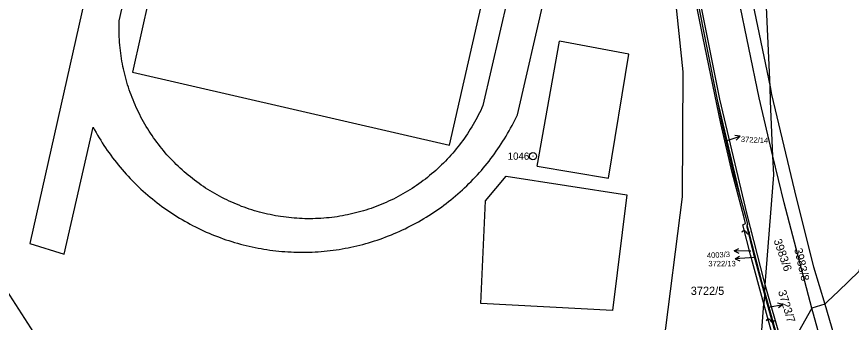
# Model space of a CAD drawing. Extents: x -747779 to -747197, y -965543 to -964919.
# Drawn here: x -747670.1 to -747496.8, y -965237.8 to -965174.5 of the extents above; entities that cross this region are included whole.
import ezdxf

# ---------------------------------------------------------------- set-up
doc = ezdxf.new("R2010")
doc.units = 0
for name, color, linetype in [('Hranice parcel', 7, 'Continuous'), ('Parcelní čísla', 7, 'Continuous'), ('Pop  PČ popisy', 7, 'Continuous'), ('Vnitřní kresba', 7, 'Continuous'), ('Značky bodu BP', 7, 'Continuous'), ('Značky budov', 7, 'Continuous')]:
    doc.layers.add(name, color=color, linetype=linetype)

msp = doc.modelspace()

# ---------------------------------------------------------------- linework, layer by layer
at = {"layer": 'Hranice parcel'}
for p, q in [((-747530.21, -965163.73), (-747524.64, -965191.71)), ((-747524.64, -965191.71), (-747519.84, -965211.9)), ((-747681.26, -965217.18), (-747664.09, -965243.73)), ((-747514.78, -965232.07), (-747514.92, -965233.94)), ((-747514.75, -965231.66), (-747514.78, -965232.07)), ((-747514.75, -965231.66), (-747511.04, -965244.8)), ((-747502.29, -965234.04), (-747505, -965234.87))]:
    msp.add_line(p, q, dxfattribs=at)
for points in [[(-747513.05, -965203.34), (-747515.92, -965191.31), (-747520.21, -965170.52), (-747525.67, -965137.7), (-747528.61, -965118.1), (-747531.3, -965092.39), (-747532.87, -965073.71), (-747533.98, -965052.7), (-747534.7, -965029.05), (-747536.67, -965009.71), (-747536.72, -965001.18), (-747536.76, -964995.31), (-747536.77, -964994.35), (-747535.07, -964979.91), (-747534.55, -964969.6), (-747535.47, -964951.02), (-747536.46, -964942.86), (-747538.19, -964936.51)], [(-747514.92, -965233.94), (-747517.71, -965223.84), (-747519.3, -965217.6), (-747518.74, -965217.36), (-747518.99, -965216.17), (-747521.54, -965206.73), (-747523.88, -965196.63), (-747527.58, -965178.59), (-747529.34, -965169.85), (-747531.71, -965157.18), (-747535.79, -965130.78), (-747546.28, -965062.23), (-747546.46, -965062.18)], [(-747535.74, -965242.71), (-747531.85, -965211.79), (-747531.66, -965185.87), (-747538.81, -965117.67), (-747546.28, -965074.93), (-747546.46, -965062.18)], [(-747513.65, -965189), (-747514.35, -965172.47), (-747514.45, -965170.1), (-747522.38, -965119.84), (-747530.45, -965066.92)], [(-747530.45, -965066.92), (-747530.18, -965073.53), (-747528.7, -965091.91), (-747525.96, -965117.41), (-747523.14, -965137.31), (-747517.53, -965170.11), (-747513.65, -965189)], [(-747487.95, -965176.49), (-747489.26, -965206.38), (-747495.23, -965227.3), (-747499.46, -965231.34), (-747501.73, -965233.5), (-747502.29, -965234.04)], [(-747513.05, -965203.34), (-747513.53, -965191.97), (-747513.65, -965189)], [(-747513.65, -965189), (-747513.32, -965190.63), (-747508.25, -965211.99), (-747504.62, -965226.28), (-747502.29, -965234.04)], [(-747524.64, -965191.71), (-747523.65, -965196.56), (-747521.27, -965206.66), (-747519.84, -965211.9)], [(-747514.75, -965231.66), (-747514.63, -965230.04), (-747512.88, -965207.25), (-747513.05, -965203.34)], [(-747505, -965234.87), (-747510.73, -965213.04), (-747513.05, -965203.34)], [(-747519.84, -965211.9), (-747518.7, -965216.08), (-747518.34, -965217.56), (-747518.44, -965217.6)], [(-747518.44, -965217.6), (-747518.48, -965218.05), (-747517.11, -965223.71), (-747514.78, -965232.07)], [(-747518.44, -965217.6), (-747515.39, -965229.37), (-747514.75, -965231.66)], [(-747514.78, -965232.07), (-747511.25, -965244.76), (-747511.35, -965244.91)], [(-747516.6, -965252.37), (-747515.34, -965239.4), (-747514.92, -965233.94)], [(-747516.6, -965252.37), (-747515.81, -965251.13), (-747515.95, -965251.03), (-747511.95, -965244.73), (-747514.92, -965233.94)], [(-747505, -965234.87), (-747510.48, -965244.69), (-747511.04, -965244.8)]]:
    msp.add_lwpolyline(points, dxfattribs=at)
at = {"layer": 'Pop  PČ popisy'}
for p, q in [((-747519.87, -965199.26), (-747520.97, -965199.1)), ((-747522.72, -965200.19), (-747519.87, -965199.26)), ((-747519.87, -965199.26), (-747520.66, -965200.05)), ((-747521.11, -965222.98), (-747520.1, -965222.49)), ((-747518.11, -965223.03), (-747521.11, -965222.98)), ((-747521.11, -965222.98), (-747520.12, -965223.5)), ((-747517.64, -965223.05), (-747518.11, -965223.03)), ((-747520.91, -965224.65), (-747519.95, -965224.08)), ((-747517.92, -965224.44), (-747520.91, -965224.65)), ((-747520.91, -965224.65), (-747519.88, -965225.08)), ((-747516.84, -965224.36), (-747517.92, -965224.44)), ((-747510.99, -965234.12), (-747512.07, -965233.82)), ((-747513.94, -965234.69), (-747510.99, -965234.12)), ((-747510.99, -965234.12), (-747511.88, -965234.8))]:
    msp.add_line(p, q, dxfattribs=at)
at = {"layer": 'Vnitřní kresba'}
for p, q in [((-747632.83, -965068.52), (-747667.34, -965221.45)), ((-747623.25, -965083.71), (-747646.03, -965185.94)), ((-747648.77, -965175.31), (-747629.51, -965090.06)), ((-747580.16, -965201.09), (-747556.88, -965098.9)), ((-747554.23, -965109.88), (-747573.25, -965192.86)), ((-747566.1, -965194.79), (-747546.86, -965111.5)), ((-747524.05, -965191.58), (-747529.66, -965163.6)), ((-747561.99, -965205.42), (-747557.35, -965179.56)), ((-747542.98, -965182.26), (-747557.35, -965179.56)), ((-747547.21, -965207.91), (-747542.98, -965182.26)), ((-747646.03, -965185.94), (-747580.16, -965201.09)), ((-747518.39, -965215.47), (-747524.05, -965191.58)), ((-747660.21, -965223.66), (-747654.19, -965197.38)), ((-747561.99, -965205.42), (-747547.21, -965207.91)), ((-747572.74, -965212.66), (-747568.4, -965207.5)), ((-747568.4, -965207.5), (-747543.4, -965211.4)), ((-747573.69, -965233.88), (-747572.74, -965212.66)), ((-747543.4, -965211.4), (-747546.37, -965235.34)), ((-747514.86, -965229.21), (-747518.39, -965215.47)), ((-747667.34, -965221.45), (-747660.21, -965223.66)), ((-747514.63, -965230.04), (-747514.86, -965229.21)), ((-747510.48, -965244.69), (-747514.63, -965230.04)), ((-747546.37, -965235.34), (-747573.69, -965233.88)), ((-747500.75, -965249.85), (-747505, -965234.87)), ((-747502.29, -965234.04), (-747497.81, -965248.91))]:
    msp.add_line(p, q, dxfattribs=at)
for points in [[(-747619.62, -965214.97), (-747620.16, -965214.82), (-747620.7, -965214.67), (-747621.23, -965214.5), (-747621.77, -965214.33), (-747622.3, -965214.15), (-747622.82, -965213.96), (-747623.35, -965213.77), (-747623.87, -965213.56), (-747624.39, -965213.35), (-747624.9, -965213.14), (-747625.42, -965212.91), (-747625.93, -965212.68), (-747626.43, -965212.44), (-747626.93, -965212.2), (-747627.43, -965211.94), (-747627.93, -965211.68), (-747628.42, -965211.42), (-747628.91, -965211.14), (-747629.39, -965210.86), (-747629.87, -965210.57), (-747630.35, -965210.28), (-747630.82, -965209.98), (-747631.28, -965209.67), (-747631.75, -965209.36), (-747632.2, -965209.04), (-747632.66, -965208.71), (-747633.11, -965208.37), (-747633.55, -965208.03), (-747633.99, -965207.69), (-747634.43, -965207.33), (-747634.85, -965206.98), (-747635.28, -965206.61), (-747635.7, -965206.24), (-747636.11, -965205.86), (-747636.52, -965205.48), (-747636.92, -965205.09), (-747637.32, -965204.7), (-747637.71, -965204.3), (-747638.1, -965203.89), (-747638.48, -965203.48), (-747638.85, -965203.07), (-747639.22, -965202.65), (-747639.58, -965202.22), (-747639.94, -965201.79), (-747640.29, -965201.35), (-747640.63, -965200.91), (-747640.97, -965200.47), (-747641.3, -965200.02), (-747641.63, -965199.56), (-747641.95, -965199.1), (-747642.26, -965198.64), (-747642.56, -965198.17), (-747642.86, -965197.69), (-747643.15, -965197.22), (-747643.44, -965196.73), (-747643.71, -965196.25), (-747643.99, -965195.76), (-747644.25, -965195.27), (-747644.51, -965194.77), (-747644.76, -965194.27), (-747645, -965193.77), (-747645.24, -965193.26), (-747645.47, -965192.75), (-747645.69, -965192.23), (-747645.9, -965191.72), (-747646.11, -965191.2), (-747646.31, -965190.68), (-747646.5, -965190.15), (-747646.68, -965189.62), (-747646.86, -965189.09), (-747647.03, -965188.56), (-747647.19, -965188.02), (-747647.35, -965187.48), (-747647.49, -965186.95), (-747647.63, -965186.4), (-747647.76, -965185.86), (-747647.89, -965185.31), (-747648, -965184.77), (-747648.11, -965184.22), (-747648.21, -965183.67), (-747648.3, -965183.11), (-747648.39, -965182.56), (-747648.46, -965182.01), (-747648.53, -965181.45), (-747648.59, -965180.9), (-747648.65, -965180.34), (-747648.69, -965179.78), (-747648.73, -965179.22), (-747648.76, -965178.67), (-747648.78, -965178.11), (-747648.8, -965177.55), (-747648.8, -965176.99), (-747648.8, -965176.43), (-747648.79, -965175.87), (-747648.77, -965175.31)], [(-747573.25, -965192.86), (-747573.48, -965193.37), (-747573.72, -965193.88), (-747573.96, -965194.38), (-747574.21, -965194.88), (-747574.47, -965195.38), (-747574.74, -965195.87), (-747575.01, -965196.36), (-747575.29, -965196.84), (-747575.58, -965197.32), (-747575.87, -965197.8), (-747576.17, -965198.27), (-747576.48, -965198.74), (-747576.79, -965199.2), (-747577.11, -965199.66), (-747577.44, -965200.11), (-747577.77, -965200.56), (-747578.11, -965201.01), (-747578.45, -965201.45), (-747578.81, -965201.88), (-747579.16, -965202.31), (-747579.53, -965202.74), (-747579.9, -965203.16), (-747580.27, -965203.57), (-747580.65, -965203.98), (-747581.04, -965204.39), (-747581.43, -965204.79), (-747581.83, -965205.18), (-747582.24, -965205.57), (-747582.65, -965205.95), (-747583.06, -965206.32), (-747583.48, -965206.69), (-747583.91, -965207.05), (-747584.34, -965207.41), (-747584.77, -965207.76), (-747585.21, -965208.11), (-747585.66, -965208.45), (-747586.11, -965208.78), (-747586.56, -965209.1), (-747587.02, -965209.43), (-747587.48, -965209.74), (-747587.95, -965210.04), (-747588.42, -965210.34), (-747588.9, -965210.64), (-747589.38, -965210.92), (-747589.87, -965211.2), (-747590.35, -965211.47), (-747590.85, -965211.74), (-747591.34, -965212), (-747591.84, -965212.25), (-747592.35, -965212.49), (-747592.85, -965212.73), (-747593.36, -965212.96), (-747593.88, -965213.19), (-747594.39, -965213.4), (-747594.91, -965213.61), (-747595.43, -965213.81), (-747595.96, -965214), (-747596.49, -965214.19), (-747597.02, -965214.37), (-747597.55, -965214.54), (-747598.08, -965214.7), (-747598.62, -965214.86), (-747599.16, -965215), (-747599.7, -965215.14), (-747600.25, -965215.28), (-747600.79, -965215.4), (-747601.34, -965215.52), (-747601.89, -965215.63), (-747602.44, -965215.73), (-747602.99, -965215.82), (-747603.54, -965215.91), (-747604.09, -965215.99), (-747604.65, -965216.06), (-747605.21, -965216.12), (-747605.76, -965216.18), (-747606.32, -965216.22), (-747606.88, -965216.26), (-747607.44, -965216.29), (-747608, -965216.32), (-747608.56, -965216.33), (-747609.11, -965216.34), (-747609.67, -965216.34), (-747610.23, -965216.33), (-747610.79, -965216.31), (-747611.35, -965216.29), (-747611.91, -965216.25), (-747612.47, -965216.21), (-747613.03, -965216.16), (-747613.58, -965216.11), (-747614.14, -965216.04), (-747614.69, -965215.97), (-747615.25, -965215.89), (-747615.8, -965215.8), (-747616.35, -965215.71), (-747616.9, -965215.61), (-747617.45, -965215.49), (-747617.99, -965215.38), (-747618.54, -965215.25), (-747619.08, -965215.11), (-747619.62, -965214.97)], [(-747601.26, -965222.35), (-747600.65, -965222.22), (-747600.04, -965222.09), (-747599.42, -965221.95), (-747598.82, -965221.8), (-747598.21, -965221.65), (-747597.6, -965221.48), (-747597, -965221.31), (-747596.4, -965221.13), (-747595.8, -965220.95), (-747595.21, -965220.75), (-747594.61, -965220.55), (-747594.02, -965220.34), (-747593.44, -965220.12), (-747592.85, -965219.9), (-747592.27, -965219.67), (-747591.69, -965219.43), (-747591.11, -965219.18), (-747590.54, -965218.93), (-747589.97, -965218.67), (-747589.41, -965218.4), (-747588.84, -965218.12), (-747588.28, -965217.84), (-747587.73, -965217.55), (-747587.18, -965217.26), (-747586.63, -965216.95), (-747586.08, -965216.64), (-747585.54, -965216.32), (-747585.01, -965216), (-747584.47, -965215.67), (-747583.95, -965215.33), (-747583.42, -965214.98), (-747582.91, -965214.63), (-747582.39, -965214.28), (-747581.88, -965213.91), (-747581.38, -965213.54), (-747580.88, -965213.16), (-747580.38, -965212.78), (-747579.89, -965212.39), (-747579.4, -965211.99), (-747578.92, -965211.59), (-747578.45, -965211.19), (-747577.98, -965210.77), (-747577.51, -965210.35), (-747577.05, -965209.93), (-747576.6, -965209.49), (-747576.15, -965209.06), (-747575.71, -965208.61), (-747575.27, -965208.17), (-747574.84, -965207.71), (-747574.41, -965207.25), (-747573.99, -965206.79), (-747573.58, -965206.32), (-747573.17, -965205.84), (-747572.77, -965205.36), (-747572.37, -965204.87), (-747571.98, -965204.38), (-747571.6, -965203.89), (-747571.22, -965203.39), (-747570.85, -965202.88), (-747570.49, -965202.37), (-747570.13, -965201.86), (-747569.78, -965201.34), (-747569.44, -965200.81), (-747569.1, -965200.29), (-747568.77, -965199.76), (-747568.44, -965199.22), (-747568.13, -965198.68), (-747567.82, -965198.13), (-747567.51, -965197.59), (-747567.21, -965197.03), (-747566.93, -965196.48), (-747566.64, -965195.92), (-747566.37, -965195.36), (-747566.1, -965194.79)], [(-747654.19, -965197.38), (-747653.89, -965197.93), (-747653.58, -965198.47), (-747653.27, -965199.02), (-747652.95, -965199.56), (-747652.62, -965200.09), (-747652.28, -965200.62), (-747651.94, -965201.14), (-747651.59, -965201.66), (-747651.24, -965202.18), (-747650.87, -965202.69), (-747650.51, -965203.2), (-747650.13, -965203.7), (-747649.75, -965204.2), (-747649.36, -965204.69), (-747648.97, -965205.18), (-747648.57, -965205.66), (-747648.17, -965206.14), (-747647.75, -965206.61), (-747647.33, -965207.08), (-747646.91, -965207.54), (-747646.48, -965207.99), (-747646.05, -965208.45), (-747645.61, -965208.89), (-747645.16, -965209.33), (-747644.71, -965209.77), (-747644.25, -965210.19), (-747643.79, -965210.61), (-747643.32, -965211.03), (-747642.84, -965211.44), (-747642.37, -965211.85), (-747641.88, -965212.24), (-747641.39, -965212.64), (-747640.9, -965213.02), (-747640.4, -965213.4), (-747639.9, -965213.77), (-747639.39, -965214.14), (-747638.88, -965214.5), (-747638.36, -965214.85), (-747637.84, -965215.2), (-747637.31, -965215.54), (-747636.78, -965215.88), (-747636.25, -965216.2), (-747635.71, -965216.52), (-747635.17, -965216.84), (-747634.62, -965217.14), (-747634.07, -965217.44), (-747633.52, -965217.73), (-747632.96, -965218.02), (-747632.4, -965218.3), (-747631.83, -965218.57), (-747631.26, -965218.83), (-747630.69, -965219.09), (-747630.12, -965219.34), (-747629.54, -965219.58), (-747628.96, -965219.81), (-747628.37, -965220.04), (-747627.79, -965220.26), (-747627.2, -965220.47), (-747626.6, -965220.68), (-747626.01, -965220.87), (-747625.41, -965221.06), (-747624.81, -965221.25), (-747624.21, -965221.42), (-747623.61, -965221.59), (-747623, -965221.74), (-747622.39, -965221.9), (-747621.78, -965222.04), (-747621.17, -965222.18), (-747620.56, -965222.3), (-747619.94, -965222.42), (-747619.33, -965222.54), (-747618.71, -965222.64), (-747618.09, -965222.74), (-747617.47, -965222.83), (-747616.85, -965222.91), (-747616.23, -965222.98), (-747615.6, -965223.05), (-747614.98, -965223.1), (-747614.35, -965223.15), (-747613.73, -965223.19), (-747613.1, -965223.23), (-747612.48, -965223.25), (-747611.85, -965223.27), (-747611.22, -965223.28), (-747610.6, -965223.28), (-747609.97, -965223.27), (-747609.35, -965223.26), (-747608.72, -965223.24), (-747608.09, -965223.21), (-747607.47, -965223.17), (-747606.84, -965223.12), (-747606.22, -965223.07), (-747605.6, -965223.01), (-747604.97, -965222.94), (-747604.35, -965222.86), (-747603.73, -965222.77), (-747603.11, -965222.68), (-747602.49, -965222.58), (-747601.88, -965222.47), (-747601.26, -965222.35)]]:
    msp.add_lwpolyline(points, dxfattribs=at)
at = {"layer": 'Značky bodu BP'}
for radius in [0.75, 0.03]:
    msp.add_circle((-747562.86, -965203.37), radius, dxfattribs=at)
at = {"layer": 'Značky budov'}
for p, q in [((-747518.74, -965219.01), (-747518.54, -965219.27)), ((-747513.68, -965237.31), (-747513.48, -965237.57))]:
    msp.add_line(p, q, dxfattribs=at)
for centre, start, end in [((-747519.08, -965219.2), 29.2914, 181.2189), ((-747518.2, -965219.08), 209.2914, 1.2189), ((-747514.02, -965237.5), 29.2914, 181.2189), ((-747513.14, -965237.38), 209.2914, 1.2189)]:
    msp.add_arc(centre, 0.394, start, end, dxfattribs=at)

# ---------------------------------------------------------------- texts
at = {"layer": 'Parcelní čísla'}
for s, height, rotation, p in [('3722/14', 1.139, 357, (-747519.73, -965200.42)), ('3983/6', 1.7, 289, (-747512.92, -965220.83)), ('4003/3', 1.139, 3, (-747526.73, -965224.51)), ('3983/8', 1.7, 283, (-747508.64, -965222.62)), ('3723/7', 1.7, 287, (-747512, -965231.4))]:
    msp.add_text(s, height=height, rotation=rotation, dxfattribs=at).set_placement(p)
for s, height, p in [('3722/13', 1.139, (-747526.45, -965226.21)), ('3722/5', 1.7, (-747530.1, -965232.12))]:
    msp.add_text(s, height=height, dxfattribs=at).set_placement(p)
at = {"layer": 'Značky bodu BP'}
msp.add_text('1046', height=1.5, dxfattribs=at).set_placement((-747568.11, -965204.12))

doc.saveas('drawing.dxf')
